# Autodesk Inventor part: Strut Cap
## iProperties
Shininess: 64.0
Length Units: 11272
Angle Units: 11279
Time Units: 11290
Mass Units: 11283
Length Display Precision: 3
Angle Display Precision: 2
Compacted: True
Part Number: Strut Cap
Document SubType Name: Modeling
Created: 2005-03
Designer: Admin
Manufacturer: Standard
Standards Organization: Custom
Density: 1 g/cm^3
Density: 0.0
Volumn: 0.0
Area: 0.0
PropertySet Name: Model Information
Control State: 0
Master: False
Checked Out: False
Author: Admin
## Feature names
1. RevolutionFull1
2. ExtrusionBlind1
3. ExtrusionBlind2
4. Hole1
5. Hole2
6. RevolutionFull2
